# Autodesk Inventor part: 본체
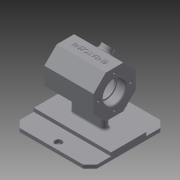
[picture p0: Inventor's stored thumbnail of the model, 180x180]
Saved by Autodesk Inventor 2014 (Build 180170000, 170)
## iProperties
Created: 2018-06
Part Number: 본체
Material: Generic
Document SubType Name: Modeling
Designer: kh
Density: 1 g/cm^3
Appearance: Default
Author: kh
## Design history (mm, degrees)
sketch "Sketch1"
  geometry: L1 (55, 55)-(-55, 55); L2 (-55, 55)-(-55, -55); L3 (-55, -55)-(55, -55); L4 (55, -55)-(55, 55); L5 (55, 55)-(-55, -55); L6 (-55, 55)-(55, -55); 1 further point
  constraints: 12 end point, 2 midpoint, 2 parallel, 1 horizontal, 1 perpendicular
  dimensions: "d0" = 110 distance of L1.start L1.end; "d1" = 110 distance of L1.end L2.end
extrude "Extrusion1" new body sketch "Sketch1" distance "d2" = 5; taper "d3" = 0 deg
sketch "Sketch2"
  geometry: L1 (55, 25)-(-55, 25); L2 (-55, 25)-(-55, -25); L3 (-55, -25)-(55, -25); L4 (55, -25)-(55, 25); L5 (55, 25)-(-55, -25); L6 (-55, 25)-(55, -25); 1 further point
  constraints: 12 end point, 2 midpoint, 2 parallel, 1 horizontal, 1 perpendicular
  dimensions: "d4" = 50 distance of L1.end L2.end; "d5" = 110 distance of L1.start L1.end
extrude "Extrusion2" join sketch "Sketch2" distance "d6" = 5; taper "d7" = 0 deg
sketch "Sketch3"
  geometry: L1 (55, 25)-(-55, 25) reference; L2 (-55, 25)-(-55, -25) reference; L3 (-55, -25)-(55, -25) reference; L4 (55, -25)-(55, 25) reference; L5 (-55, 0)-(55, 0); L6 (55, 55)-(-55, 55) reference; 4 further points
  constraints: 3 midpoint, 2 end point, 1 symmetric about line, 1 vertical alignment
  dimensions: "d8" = 10 distance from line of point (0, 45) L6
hole "Hole1" sketch "Sketch3" at (0, 45), (0, -45) diameter "d9" = 10; stored, may be unused: countersink angle "d13" = 90 deg, drill point angle "d15" = 118 deg; dims "d10" = 6, "d11" = 4, "d12" = 2, "d14" = 8
chamfer "Chamfer1" distance "d16" = 10; stored, may be unused: second distance "d17" = 2, angle "d18" = 45 deg
workplane "Work Plane2"
sketch "Sketch6" dims "d25" = 60
  geometry: L1 (-45, 0)-(45, 0) reference; L2 (12.426, 92)-(30, 74.426); L3 (30, 74.426)-(30, 49.574); L4 (30, 49.574)-(12.426, 32); L5 (12.426, 32)-(-12.426, 32); L6 (-12.426, 32)-(-30, 49.574); L7 (-30, 49.574)-(-30, 74.426); L8 (-30, 74.426)-(-12.426, 92); L9 (-12.426, 92)-(12.426, 92); 7 further points
  constraints: 16 end point, 3 coincident, 3 vertical alignment, 2 midpoint, 19 other
  dimensions: "d26" = 62 distance from line of L1 point (0, 62)
extrude "Extrusion3" join sketch "Sketch6" distance "d27" = 70; taper "d28" = 0 deg
sketch "Sketch8"
  geometry: L1 (92, 12.426)-(92, -12.426) reference; L2 (74.426, 30)-(92, 12.426) reference; L3 (49.574, 30)-(74.426, 30) reference; L4 (32, 12.426)-(49.574, 30) reference; L5 (32, -12.426)-(32, 12.426) reference; L6 (49.574, -30)-(32, -12.426) reference; L7 (74.426, -30)-(49.574, -30) reference; L8 (92, -12.426)-(74.426, -30) reference; L9 (32, 0)-(92, 0); C1 r 16 at (62, 0); 2 further points
  constraints: 3 midpoint, 2 end point, 1 centre point, 1 coincident
  dimensions: "d29" = 32 diameter of C1
extrude "Extrusion4" cut sketch "Sketch8" distance "d30" = 12; taper "d31" = 0 deg
sketch "Sketch9"
  geometry: C1 r 16 at (0, 0) reference; C2 r 14 at (0, 0); 1 further point
  constraints: 1 centre point, 1 coincident
  dimensions: "d32" = 28 diameter of C2
extrude "Extrusion5" cut sketch "Sketch9" distance "d33" = 3; taper "d34" = 0 deg
sketch "Sketch10"
  geometry: C1 r 14 at (0, 0) reference; C2 r 25 at (0, 0); 1 further point
  constraints: 1 centre point, 1 coincident
  dimensions: "d35" = 50 diameter of C2
extrude "Extrusion6" cut sketch "Sketch10" distance "d36" = 40; taper "d37" = 0 deg
sketch "Sketch11"
  geometry: C1 r 25 at (-62, 0) reference; C2 r 16 at (-62, 0); 1 further point
  constraints: 1 centre point, 1 coincident
  dimensions: "d38" = 32 diameter of C2
extrude "Extrusion7" cut sketch "Sketch11" distance "d39" = 12; taper "d40" = 0 deg
sketch "Sketch12"
  geometry: C1 r 16 at (0, 0) reference; C2 r 14 at (0, 0); 1 further point
  constraints: 1 centre point, 1 coincident
  dimensions: "d41" = 28 diameter of C2
extrude "Extrusion8" cut sketch "Sketch12" distance "d42" = 3; taper "d43" = 0 deg
sketch "Sketch13" dims "d44" = 46
  geometry: L1 (-92, 12.426)-(-92, -12.426) reference; L2 (-92, -12.426)-(-74.426, -30) reference; L3 (-74.426, -30)-(-49.574, -30) reference; L4 (-49.574, -30)-(-32, -12.426) reference; L5 (-32, -12.426)-(-32, 12.426) reference; L6 (-32, 12.426)-(-49.574, 30) reference; L7 (-49.574, 30)-(-74.426, 30) reference; L8 (-74.426, 30)-(-92, 12.426) reference; L9 (-62, 0)-(-85, 0); C1 r 16 at (-62, 0) reference; 2 further points
  constraints: 2 coincident, 2 end point, 1 horizontal alignment, 1 parallel, 2 other
hole "Hole2" sketch "Sketch13" at (-85, 0) diameter "d45" = 3.459; stored, may be unused: countersink angle "d49" = 90 deg, drill point angle "d51" = 118 deg; dims "d46" = 8, "d47" = 4, "d48" = 2, "d50" = 10
pattern_circular "Circular Pattern1" dims angle "d53" = 360 deg
workplane "Work Plane4"
mirror "Mirror1"
sketch "Sketch14"
  geometry: L1 (-62, 0)-(-97.146, 0); L2 (-62, 0)-(-88.163, 26.163); L3 (-74.426, 30)-(-92, 12.426) reference; L4 (-81.69, 32.636)-(-94.636, 19.69); C1 r 14 at (-62, 0) reference; C2 r 25 at (-62, 0) reference; 1 further point
  constraints: 6 end point, 1 horizontal, 1 midpoint, 1 parallel
  dimensions: "d56" = 45 deg angle of L2 L1; "d57" = 7 distance from line of L2.end L3
  node "Projected Loop7"
workplane "Work Plane5"
sketch "Sketch15"
  geometry: L1 (0, 9.154)-(0, -9.154) reference; C1 r 8 at (0, 0); 1 further point
  constraints: 1 centre point, 1 midpoint
  dimensions: "d58" = 16 diameter of C1
extrude "Extrusion9" join sketch "Sketch15" stored distance "d59" = 3; taper "d60" = 0 deg
hole "Hole3" diameter "d63" = 8; stored, may be unused: countersink angle "d67" = 90 deg, drill point angle "d69" = 0 deg; dims "d61" = 10, "d62" = 10, "d64" = 8, "d65" = 4, "d66" = 2, "d68" = 10
chamfer "Chamfer2" distance "d70" = 1; stored, may be unused: second distance "d71" = 2, angle "d72" = 45 deg
fillet "Fillet1" dims "d73" = 0.3
fillet "Fillet2" dims "d74" = 3
sketch "Sketch16"
  geometry: L1 (-19, 0)-(19, 0); L2 (-19, 5)-(19, 5); L3 (19, -5)-(-19, -5); A1 r 5 centre (-19, 0) between (-19, 5) and (-19, -5); A2 r 5 centre (19, 0) between (19, -5) and (19, 5); 2 further points
  constraints: 8 end point, 4 point on circle, 4 tangent, 2 centre point, 1 coincident, 1 horizontal, 1 midpoint, 1 parallel
  dimensions: "d75" = 38 distance of L1.end L1.start; "d76" = 5 radius of A1
extrude "Extrusion10" join sketch "Sketch16" stored distance "d77" = 0; taper "d78" = 0 deg
fillet "Fillet3" dims "d79" = 3
sketch "Sketch17"
  geometry: 2 further points
  constraints: 1 coincident, 1 other
emboss "Emboss1" sketch "Sketch17" dims "d0" = 110, "d1" = 110, "d80" = 0.5, "d81" = 0
body "Solid1"
node "Projected Loop1"
node "Projected Loop2"
node "Projected Loop3"
node "Projected Loop4"
node "Projected Loop5"
node "Projected Loop6"
other parameters: "d22" = -35
